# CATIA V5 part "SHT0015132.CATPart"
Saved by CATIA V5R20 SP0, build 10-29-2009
Part number: Part7
Bounding box of the stored display mesh (mm): x 125.5 to 161, y -42 to 42, z 10 to 28
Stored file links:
  F:\38-福田A6\1-数据\6-冻结数据\第九批\设变\转盘解锁机构设变-ECR0011834-20250805\更改后\SHT0015132-气动转盘解锁安装钣金\SHT0015132.CATPart
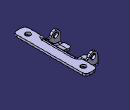
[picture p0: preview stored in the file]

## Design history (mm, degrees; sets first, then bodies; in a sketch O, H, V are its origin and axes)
Body1 (main body)
Body2 "更改后-20250805"
  Solid1: solid without history
  Thickness1: Thickness 0.05, Face face of Solid1
  Thickness2: Thickness 0.05, Face face of Solid1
